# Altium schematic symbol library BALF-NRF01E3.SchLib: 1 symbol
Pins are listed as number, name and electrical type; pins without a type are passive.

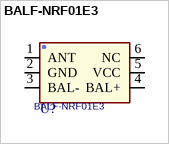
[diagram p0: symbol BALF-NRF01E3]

## BALF-NRF01E3
designator U?
footprint ST_LGA6R50P2X3_160X110X48
pins: 1 ANT, 2 GND, 3 BAL-, 4 BAL+, 5 VCC, 6 NC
